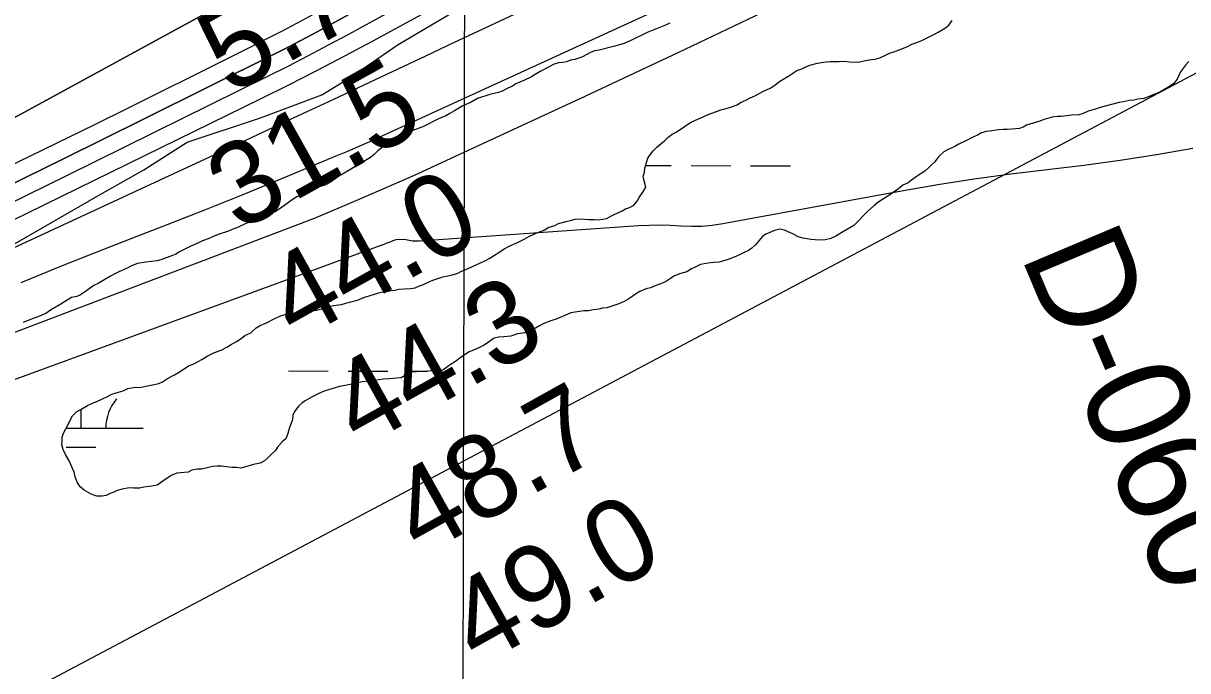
# Model space of a CAD drawing. Extents: x 3177385 to 3215275, y 903885 to 929304.
# Drawn here: x 3191696 to 3192634, y 909863 to 910384 of the extents above; entities that cross this region are included whole.
import ezdxf

# ---------------------------------------------------------------- set-up
doc = ezdxf.new("R2010")
doc.units = 0
for name, color, linetype in [('V-GRID-MAJR', 7, 'Continuous'), ('V-RIVR-EDGE', 7, 'Continuous'), ('V-RIVR-RANG', 7, 'Continuous'), ('V-RIVR-RANG-IDEN', 7, 'Continuous'), ('V-SITE-VEGE', 7, 'Continuous'), ('V-TOPO-BNDY', 7, 'Continuous'), ('V-TOPO-DPTH', 7, 'Continuous'), ('V-TOPO-MAJR', 7, 'Continuous'), ('V-TOPO-MINR', 7, 'Continuous'), ('V-TOPO-WATR', 7, 'Continuous'), ('V-WETL-SWMP', 7, 'Continuous')]:
    doc.layers.add(name, color=color, linetype=linetype)

msp = doc.modelspace()

# ---------------------------------------------------------------- linework, layer by layer
at = {"layer": 'V-GRID-MAJR'}
msp.add_spline([(3192048.7, 909312.78), (3192063.69, 915372.62), (3192078.68, 921435.55), (3192093.67, 927498.52), (3192093.68, 927501.56)], degree=3, dxfattribs=at)
at = {"layer": 'V-RIVR-EDGE'}
msp.add_lwpolyline([(3191682.14, 910203.16), (3191755.71, 910245.57), (3191792.71, 910266.35), (3191827.54, 910288.86), (3191886.7, 910308.28), (3191936.3, 910326.85), (3191958.94, 910340.7), (3191997.69, 910367.55), (3192065.17, 910407.38), (3192148.3, 910451.94), (3192242.33, 910509.96), (3192325.92, 910560.17), (3192385.98, 910590.89), (3192445.62, 910628.56), (3192497.01, 910665.38), (3192548.4, 910708.72), (3192599.37, 910750.32), (3192650.72, 910773.67)], dxfattribs=at)
at = {"layer": 'V-SITE-VEGE'}
for p, q in [((3192213.22, 910383.04), (3192206.4, 910380.34)), ((3192216.53, 910384.5), (3192213.22, 910383.04)), ((3192198.46, 910377.02), (3192184.56, 910370.33)), ((3192206.4, 910380.34), (3192198.46, 910377.02)), ((3192171.15, 910365.81), (3192159.73, 910362.78)), ((3192179.06, 910368.04), (3192171.15, 910365.81)), ((3192184.56, 910370.33), (3192179.06, 910368.04)), ((3192136.63, 910354.75), (3192133.33, 910353.51)), ((3192137.06, 910354.74), (3192136.63, 910354.75)), ((3192140.13, 910355.33), (3192137.06, 910354.74)), ((3192143.21, 910356.36), (3192140.13, 910355.33)), ((3192146.3, 910357.6), (3192143.21, 910356.36)), ((3192152.7, 910360.96), (3192146.3, 910357.6)), ((3192155.78, 910362.2), (3192152.7, 910360.96)), ((3192159.73, 910362.78), (3192155.78, 910362.2)), ((3192111.98, 910345.67), (3192108.21, 910343.13)), ((3192123.46, 910351.54), (3192111.98, 910345.67)), ((3192126.98, 910352.77), (3192123.46, 910351.54)), ((3192130.26, 910352.92), (3192126.98, 910352.77)), ((3192133.33, 910353.51), (3192130.26, 910352.92)), ((3192098.94, 910338.3), (3192092.55, 910335.6)), ((3192105.12, 910341.45), (3192098.94, 910338.3)), ((3192108.21, 910343.13), (3192105.12, 910341.45)), ((3192071.62, 910327.09), (3192061.5, 910323.82)), ((3192078.42, 910328.7), (3192071.62, 910327.09)), ((3192081.51, 910329.94), (3192078.42, 910328.7)), ((3192086.14, 910332.24), (3192081.51, 910329.94)), ((3192089.23, 910333.49), (3192086.14, 910332.24)), ((3192092.55, 910335.6), (3192089.23, 910333.49)), ((3192049.81, 910317.95), (3192042.95, 910313.95)), ((3192056.42, 910321.09), (3192049.81, 910317.95)), ((3192061.5, 910323.82), (3192056.42, 910321.09)), ((3192036.1, 910309.94), (3192029.71, 910307.24)), ((3192039.2, 910311.84), (3192036.1, 910309.94)), ((3192042.95, 910313.95), (3192039.2, 910311.84)), ((3192018.23, 910301.37), (3192009.42, 910298.07)), ((3192029.71, 910307.24), (3192018.23, 910301.37)), ((3191993.75, 910290.1), (3191990.87, 910288.42)), ((3191996.83, 910291.35), (3191993.75, 910290.1)), ((3192001.7, 910294.3), (3191996.83, 910291.35)), ((3192009.42, 910298.07), (3192001.7, 910294.3)), ((3191981.34, 910281.63), (3191978.44, 910278.85)), ((3191985.11, 910284.61), (3191981.34, 910281.63)), ((3191990.87, 910288.42), (3191985.11, 910284.61)), ((3191970.02, 910273.14), (3191960.07, 910267.24)), ((3191975.33, 910276.52), (3191970.02, 910273.14)), ((3191978.44, 910278.85), (3191975.33, 910276.52)), ((3191950.56, 910261.76), (3191943.24, 910256.46)), ((3191954.31, 910263.65), (3191950.56, 910261.76)), ((3191960.07, 910267.24), (3191954.31, 910263.65)), ((3191931.14, 910251.91), (3191927.17, 910250.03)), ((3191934.87, 910252.92), (3191931.14, 910251.91)), ((3191939.27, 910254.36), (3191934.87, 910252.92)), ((3191943.24, 910256.46), (3191939.27, 910254.36)), ((3191912.37, 910242.27), (3191906.16, 910237.81)), ((3191915.91, 910244.59), (3191912.37, 910242.27)), ((3191919.22, 910246.05), (3191915.91, 910244.59)), ((3191927.17, 910250.03), (3191919.22, 910246.05)), ((3191898.63, 910232.73), (3191884.32, 910227.58)), ((3191906.16, 910237.81), (3191898.63, 910232.73)), ((3191875.06, 910223.19), (3191868.22, 910220.06)), ((3191878.14, 910224.21), (3191875.06, 910223.19)), ((3191884.32, 910227.58), (3191878.14, 910224.21)), ((3191852.59, 910214.28), (3191849.29, 910213.04)), ((3191860.95, 910217.16), (3191852.59, 910214.28)), ((3191863.82, 910218.4), (3191860.95, 910217.16)), ((3191868.22, 910220.06), (3191863.82, 910218.4)), ((3191830.12, 910204.71), (3191821.51, 910200.31)), ((3191834.31, 910206.59), (3191830.12, 910204.71)), ((3191837.39, 910207.83), (3191834.31, 910206.59)), ((3191840.04, 910209.3), (3191837.39, 910207.83)), ((3191844.66, 910210.95), (3191840.04, 910209.3)), ((3191849.29, 910213.04), (3191844.66, 910210.95)), ((3191815.77, 910197.37), (3191806.53, 910194.08)), ((3191818.63, 910198.62), (3191815.77, 910197.37)), ((3191821.51, 910200.31), (3191818.63, 910198.62)), ((3191778.65, 910187.03), (3191772.69, 910184.32)), ((3191782.83, 910189.12), (3191778.65, 910187.03)), ((3191787.68, 910190.98), (3191782.83, 910189.12)), ((3191794.26, 910192.15), (3191787.68, 910190.98)), ((3191803.45, 910193.27), (3191794.26, 910192.15)), ((3191806.53, 910194.08), (3191803.45, 910193.27)), ((3191758.55, 910176.54), (3191755.89, 910174.85)), ((3191765.85, 910180.75), (3191758.55, 910176.54)), ((3191768.94, 910182.43), (3191765.85, 910180.75)), ((3191772.69, 910184.32), (3191768.94, 910182.43)), ((3191745.04, 910167.87), (3191741.72, 910165.76)), ((3191752.36, 910173.17), (3191745.04, 910167.87)), ((3191755.89, 910174.85), (3191752.36, 910173.17)), ((3191725.84, 910158.24), (3191717.66, 910153.39)), ((3191728.72, 910160.14), (3191725.84, 910158.24)), ((3191734.47, 910163.51), (3191728.72, 910160.14)), ((3191738.86, 910164.51), (3191734.47, 910163.51)), ((3191741.72, 910165.76), (3191738.86, 910164.51)), ((3191713.89, 910150.63), (3191707.28, 910147.93)), ((3191717.66, 910153.39), (3191713.89, 910150.63)), ((3191702.88, 910146.5), (3191695.61, 910143.59)), ((3191707.28, 910147.93), (3191702.88, 910146.5))]:
    msp.add_line(p, q, dxfattribs=at)
at = {"layer": 'V-TOPO-BNDY'}
msp.add_lwpolyline([(3212104.8, 927454.99), (3211654.69, 925302.34), (3210557.14, 922651.35), (3209209.28, 920082.76), (3207894.02, 918536.94), (3206268.96, 917198.21), (3204189.96, 915875.19), (3202488.97, 914709.68), (3200913.97, 913922.16), (3198614.47, 912914.15), (3196094.47, 911748.64), (3194267.47, 911118.63), (3192912.97, 910488.63), (3191155.59, 909558.24), (3212939.67, 909531.52)], dxfattribs=at)
at = {"layer": 'V-TOPO-DPTH'}
for points in [[(3190594.76, 909767.6), (3190671.75, 909798.31), (3190886.03, 909887.07), (3190887.1, 909887.53), (3190890.24, 909888.99), (3191053.07, 909970.07), (3191135.29, 910011.58), (3191217.19, 910053.7), (3191298.62, 910096.72), (3191379.74, 910140.34), (3191862.17, 910403.27), (3191876.76, 910411.21), (3191891.35, 910419.14), (3191905.95, 910427.05), (3191920.56, 910434.96), (3192264.2, 910620.72), (3192356.7, 910671.14), (3192448.97, 910721.98), (3192540.88, 910773.46), (3192632.56, 910825.36), (3192780.37, 910909.72)], [(3192780.37, 910909.72), (3192632.56, 910825.36), (3192540.88, 910773.46), (3192448.97, 910721.98), (3192356.7, 910671.14), (3192264.2, 910620.72), (3191920.56, 910434.96), (3191905.95, 910427.05), (3191891.35, 910419.14), (3191876.76, 910411.21), (3191862.17, 910403.27), (3191379.74, 910140.34), (3191298.62, 910096.72), (3191217.19, 910053.7), (3191135.29, 910011.58), (3191053.07, 909970.07), (3190890.24, 909888.99), (3190887.1, 909887.53), (3190886.03, 909887.07), (3190671.75, 909798.31), (3190594.76, 909767.6)], [(3190773.81, 909825.22), (3190881.11, 909873.05), (3190887.07, 909875.73), (3190893.01, 909878.44), (3190898.94, 909881.19), (3190904.85, 909883.96), (3191537.07, 910183.08), (3191601.03, 910213.58), (3191664.85, 910244.35), (3191728.49, 910275.51), (3191791.99, 910306.94), (3191898.29, 910359.95), (3191908.52, 910365.13), (3191918.71, 910370.39), (3191928.83, 910375.77), (3191938.91, 910381.24), (3192121.67, 910481.72), (3192222.94, 910537.78), (3192323.99, 910594.23), (3192424.7, 910651.27), (3192525.2, 910708.7), (3192802.32, 910868.12)], [(3192802.32, 910868.12), (3192525.2, 910708.7), (3192424.7, 910651.27), (3192323.99, 910594.23), (3192222.94, 910537.78), (3192121.67, 910481.72), (3191938.91, 910381.24), (3191928.83, 910375.77), (3191918.71, 910370.39), (3191908.52, 910365.13), (3191898.29, 910359.95), (3191791.99, 910306.94), (3191728.49, 910275.51), (3191664.85, 910244.35), (3191601.03, 910213.58), (3191537.07, 910183.08), (3190904.85, 909883.96), (3190898.94, 909881.19), (3190893.01, 909878.44), (3190887.07, 909875.73), (3190881.11, 909873.05), (3190773.81, 909825.22)], [(3189907.85, 909317.76), (3190786.54, 909802.18), (3190846.26, 909830.37), (3190874.99, 909843.88), (3190903.74, 909857.33), (3190932.53, 909870.71), (3190961.34, 909884.03), (3191160.92, 909975.94), (3191289.34, 910035.62), (3191417.47, 910095.9), (3191545.17, 910157.07), (3191672.6, 910218.83), (3191886.81, 910323.58), (3191909.55, 910334.88), (3191932.19, 910346.38), (3191954.68, 910358.18), (3191977.06, 910370.17), (3192774.87, 910804.33)]]:
    msp.add_lwpolyline(points, dxfattribs=at)
at = {"layer": 'V-TOPO-MAJR'}
msp.add_lwpolyline([(3191330.66, 909999.44), (3191930.38, 910227.54), (3191958.09, 910239.21), (3191985.69, 910251.11), (3192013.15, 910263.35), (3192040.51, 910275.81), (3192144.35, 910323.91), (3192223.38, 910360.95), (3192302.17, 910398.48), (3192380.62, 910436.73), (3192458.83, 910475.47), (3192878.95, 910685.93)], dxfattribs=at)
at = {"layer": 'V-TOPO-MINR'}
for points in [[(3190594.76, 909767.6), (3190671.75, 909798.31), (3190886.03, 909887.07), (3190887.1, 909887.53), (3190890.24, 909888.99), (3191053.07, 909970.07), (3191135.29, 910011.58), (3191217.19, 910053.7), (3191298.62, 910096.72), (3191379.74, 910140.34), (3191862.17, 910403.27), (3191876.76, 910411.21), (3191891.35, 910419.14), (3191905.95, 910427.05), (3191920.56, 910434.96), (3192264.2, 910620.72), (3192356.7, 910671.14), (3192448.97, 910721.98), (3192540.88, 910773.46), (3192632.56, 910825.36), (3192780.37, 910909.72)], [(3189797.72, 909318.02), (3190760.57, 909827.55), (3190883.54, 909880.14), (3190887.06, 909881.68), (3190890.57, 909883.25), (3190894.05, 909884.88), (3190897.52, 909886.53), (3191753.14, 910303.1), (3191779.72, 910316.11), (3191806.26, 910329.19), (3191832.74, 910342.37), (3191859.19, 910355.64), (3191903.92, 910378.18), (3191907.97, 910380.25), (3191912, 910382.34), (3191916, 910384.48), (3191919.99, 910386.65), (3191990.96, 910425.75), (3192030.35, 910447.62), (3192069.63, 910469.67), (3192108.77, 910491.99), (3192147.81, 910514.47), (3192771.73, 910876.71)], [(3189907.85, 909317.76), (3190786.54, 909802.18), (3190846.26, 909830.37), (3190874.99, 909843.88), (3190903.74, 909857.33), (3190932.53, 909870.71), (3190961.34, 909884.03), (3191160.92, 909975.94), (3191289.34, 910035.62), (3191417.47, 910095.9), (3191545.17, 910157.07), (3191672.6, 910218.83), (3191886.81, 910323.58), (3191909.55, 910334.88), (3191932.19, 910346.38), (3191954.68, 910358.18), (3191977.06, 910370.17), (3192774.87, 910804.33)], [(3189871.82, 909317.84), (3190780.45, 909815.09), (3190876.44, 909859.27), (3190887.1, 909864.19), (3190897.76, 909869.11), (3190908.41, 909874.04), (3190919.06, 909878.99), (3191339.99, 910074.62), (3191438.17, 910120.67), (3191536.12, 910167.19), (3191633.74, 910214.4), (3191731.13, 910262.07), (3191892.61, 910341.82), (3191909.04, 910350.07), (3191925.41, 910358.46), (3191941.66, 910367.06), (3191957.84, 910375.8), (3192458.26, 910650.34), (3192523.47, 910686.32), (3192588.58, 910722.5), (3192653.51, 910758.98)], [(3190790.59, 909788.07), (3190864.2, 909823.81), (3190886.93, 909834.75), (3190909.71, 909845.58), (3190932.57, 909856.25), (3190955.48, 909866.81), (3191108.63, 909936.75), (3191208.12, 909982.27), (3191307.56, 910027.91), (3191406.92, 910073.72), (3191506.23, 910119.63), (3191875.4, 910290.66), (3191910.32, 910306.88), (3191945.21, 910323.16), (3191980.07, 910339.51), (3192014.91, 910355.91), (3192042.63, 910369), (3192091.39, 910391.8), (3192140.26, 910414.38), (3192189.29, 910436.59), (3192238.43, 910458.58), (3192563.59, 910602.63), (3192609.86, 910623.15), (3192656.13, 910643.68)], [(3191693.89, 910175.76), (3191723.31, 910187.89), (3191752.87, 910199.65), (3191782.54, 910211.16), (3191812.23, 910222.62), (3191841.86, 910234.25), (3191871.38, 910246.13), (3191900.83, 910258.19), (3191947.75, 910277.64), (3191957.05, 910281.56), (3191966.33, 910285.54), (3191975.55, 910289.63), (3191984.75, 910293.79), (3192409.43, 910488.5), (3192495.07, 910528.26), (3192580.45, 910568.56), (3192665.44, 910609.67)], [(3191156.32, 909902.81), (3191984.07, 910205.65), (3191986.44, 910206.63), (3191988.81, 910207.6), (3191991.18, 910208.57), (3191993.55, 910209.53), (3191995.95, 910210.25), (3192000.82, 910210.64), (3192003.79, 910210.21), (3192006.54, 910209.71), (3192009.3, 910209.37), (3192012.09, 910209.28), (3192014.88, 910209.35), (3192191.47, 910221.5), (3192199.98, 910221.9), (3192208.48, 910222.05), (3192216.98, 910221.84), (3192225.48, 910221.39), (3192233.96, 910221.08), (3192242.42, 910221.2), (3192250.84, 910221.97), (3192259.25, 910223.18), (3192403.37, 910249.58), (3192432.6, 910254.6), (3192461.9, 910259.2), (3192491.28, 910263.17), (3192520.73, 910266.71), (3192550.17, 910270.26), (3192579.55, 910274.26), (3192608.83, 910278.93), (3192638.05, 910284.04)]]:
    msp.add_lwpolyline(points, dxfattribs=at)
at = {"layer": 'V-TOPO-WATR'}
msp.add_lwpolyline([(3190773.81, 909825.22), (3190881.11, 909873.05), (3190887.07, 909875.73), (3190893.01, 909878.44), (3190898.94, 909881.19), (3190904.85, 909883.96), (3191537.07, 910183.08), (3191601.03, 910213.58), (3191664.85, 910244.35), (3191728.49, 910275.51), (3191791.99, 910306.94), (3191898.29, 910359.95), (3191908.52, 910365.13), (3191918.71, 910370.39), (3191928.83, 910375.77), (3191938.91, 910381.24), (3192121.67, 910481.72), (3192222.94, 910537.78), (3192323.99, 910594.23), (3192424.7, 910651.27), (3192525.2, 910708.7), (3192802.32, 910868.12)], dxfattribs=at)
at = {"layer": 'V-WETL-SWMP'}
for p, q in [((3192197.18, 910269.96), (3192217.7, 910269.92)), ((3192233.7, 910269.88), (3192265.7, 910269.8)), ((3192281.7, 910269.77), (3192313.7, 910269.69)), ((3191909.31, 910104.46), (3191941.31, 910104.39)), ((3191957.31, 910104.35), (3191989.31, 910104.27)), ((3192005.31, 910104.24), (3192021.27, 910104.2)), ((3191742.14, 910058.42), (3191742.18, 910073.58)), ((3191730.26, 910058.45), (3191792.14, 910058.3)), ((3191730.11, 910043.02), (3191754.11, 910042.96))]:
    msp.add_line(p, q, dxfattribs=at)
for points in [[(3192254.27, 910313.43), (3192257.73, 910314.89), (3192260.8, 910315.58), (3192264.63, 910316.64), (3192270.77, 910318.8), (3192273.48, 910320.65), (3192277.71, 910322.46), (3192280.8, 910324.3), (3192285.03, 910326.12), (3192291.97, 910329.78), (3192297.36, 910332.34), (3192300.45, 910334.18), (3192305.09, 910337.51), (3192308.57, 910339.72), (3192312.44, 910342.31), (3192319, 910346.36), (3192322.84, 910347.8), (3192325.54, 910349.27), (3192329.39, 910350.71), (3192335.52, 910352.49), (3192338.58, 910352.8), (3192342.78, 910353.47), (3192345.84, 910353.79), (3192349.27, 910353.72), (3192353.08, 910353.64), (3192357.66, 910353.92), (3192361.08, 910353.47), (3192368.7, 910353.3), (3192371.76, 910354), (3192375.97, 910354.67), (3192379.03, 910355.37), (3192382.09, 910355.69), (3192385.92, 910356.75), (3192389.77, 910358.57), (3192393.62, 910360.39), (3192397.07, 910361.46), (3192403.61, 910363.99), (3192408.22, 910365.8), (3192411.69, 910367.63), (3192415.53, 910369.08), (3192420.14, 910370.88), (3192429.77, 910375.63), (3192432.86, 910377.47), (3192435.95, 910379.31), (3192438.65, 910380.78), (3192441.36, 910383.01), (3192444.11, 910386.76)], [(3192634.73, 910353.73), (3192632, 910350.74), (3192628.08, 910345.49), (3192625.28, 910339.45), (3192622.53, 910335.7), (3192617.9, 910332.75), (3192611.34, 910329.08), (3192606.73, 910327.27), (3192602.88, 910325.45), (3192598.66, 910324.01), (3192593.69, 910323.36), (3192590.62, 910322.66), (3192586.81, 910322.36), (3192582.21, 910321.31), (3192578.76, 910320.63), (3192571.49, 910318.87), (3192567.27, 910317.82), (3192562.67, 910316.39), (3192559.6, 910315.32), (3192554.61, 910313.9), (3192549.61, 910311.72), (3192546.16, 910310.65), (3192540.43, 910310.39), (3192532.03, 910309.42), (3192528.6, 910309.5), (3192524.77, 910308.82), (3192520.94, 910307.76), (3192517.88, 910307.06), (3192514.8, 910305.6), (3192504.06, 910302.4), (3192501.36, 910300.93), (3192498.29, 910299.85), (3192492.17, 910299.22), (3192488.36, 910298.92), (3192485.31, 910298.99), (3192481.49, 910298.69), (3192474.23, 910297.7), (3192471.17, 910297.38), (3192467.33, 910295.94), (3192464.63, 910294.47), (3192459.63, 910292.29), (3192455.77, 910290.09), (3192449.61, 910287.17), (3192446.14, 910285.34), (3192440.75, 910282.78), (3192437.28, 910280.95), (3192434.56, 910278.34), (3192432.22, 910275.72), (3192429.87, 910272.73), (3192427.53, 910270.49), (3192424.81, 910267.88), (3192422.09, 910265.27), (3192419, 910263.43), (3192415.13, 910260.84)], [(3191849.57, 910119.29), (3191854.94, 910121.09), (3191859.57, 910123.65), (3191862.66, 910125.49), (3191867.29, 910128.06), (3191871.16, 910130.65), (3191874.25, 910132.87), (3191878.87, 910135.06), (3191879.26, 910135.43), (3191883.15, 910139.16), (3191886.62, 910140.99), (3191891.62, 910143.17), (3191897.79, 910146.47), (3191902.41, 910148.66), (3191908.17, 910150.44), (3191911.6, 910150.75), (3191915.81, 910151.42), (3191920.77, 910151.7), (3191926.51, 910152.72), (3191931.86, 910153.37), (3191937.22, 910154.78), (3191940.3, 910155.86), (3191945.66, 910157.27), (3191952.15, 910157.89), (3191955.61, 910158.96), (3191959.44, 910160.02), (3191964.81, 910161.43), (3191970.58, 910163.98), (3191974.41, 910165.04), (3191980.17, 910166.82), (3191984, 910167.88), (3191988.59, 910168.55), (3191992.03, 910169.24), (3191995.09, 910169.55), (3191998.15, 910170.25), (3192002.73, 910170.53), (3192007.69, 910170.81), (3192011.52, 910171.49), (3192014.98, 910172.94), (3192018.05, 910174.02), (3192020.75, 910175.49), (3192025.75, 910177.67), (3192033.81, 910180.16), (3192041.47, 910181.9), (3192045.69, 910183.34), (3192048.77, 910184.8), (3192052.23, 910186.25), (3192058, 910188.79), (3192063.39, 910191.35), (3192068.01, 910193.54), (3192071.48, 910195.37), (3192074.57, 910197.21), (3192079.6, 910200.53), (3192083.07, 910202.74), (3192087.7, 910205.31), (3192093.85, 910207.85), (3192099.63, 910210.77), (3192103.49, 910212.98), (3192108.88, 910215.53), (3192115.8, 910218.05), (3192118.5, 910219.9), (3192123.88, 910221.69), (3192126.96, 910223.15), (3192133.09, 910224.93), (3192137.31, 910225.98), (3192140.37, 910226.68), (3192144.19, 910226.98), (3192151.42, 910226.44), (3192155.61, 910226.35), (3192159.04, 910226.28), (3192162.48, 910226.59), (3192165.54, 910227.28), (3192170.55, 910229.85), (3192178.25, 910233.49), (3192180.95, 910234.96), (3192184.02, 910236.04), (3192187.49, 910237.87), (3192190.23, 910241.24), (3192191.82, 910244.26), (3192195.35, 910249.14), (3192197.33, 910252.52), (3192195.91, 910257.51), (3192195.23, 910261.33), (3192196.06, 910264.37), (3192196.51, 910267.79), (3192198.97, 910275.74), (3192200.55, 910278.37), (3192203.29, 910281.74), (3192206.41, 910285.11), (3192212.23, 910289.94), (3192214.95, 910292.55), (3192218.44, 910295.14), (3192221.14, 910296.61), (3192228.09, 910301.03), (3192231.19, 910303.25), (3192233.89, 910304.72), (3192239.67, 910307.65), (3192243.51, 910309.09), (3192246.21, 910310.56), (3192250.43, 910311.99), (3192254.27, 910313.43)], [(3192415.13, 910260.84), (3192411.26, 910258.26), (3192408.55, 910256.03), (3192404.32, 910254.21), (3192400.82, 910251.24), (3192396.57, 910248.28), (3192393.86, 910246.43), (3192388.84, 910243.11), (3192384.2, 910240.16), (3192380.71, 910237.18), (3192376.05, 910233.09), (3192371.77, 910228.99), (3192369.8, 910226.36), (3192364.75, 910221.52), (3192356.64, 910216.73), (3192350.46, 910213.05), (3192346.23, 910211.24), (3192341.64, 910210.19), (3192337.06, 910209.91), (3192330.59, 910210.43), (3192324.13, 910211.33), (3192319.96, 910212.56), (3192315.82, 910214.94), (3192312.05, 910216.54), (3192309.02, 910217.75), (3192305.23, 910218.59), (3192301.01, 910217.54), (3192297.17, 910216.1), (3192294.09, 910214.64), (3192291, 910212.42), (3192285.52, 910206.05), (3192282.8, 910203.44), (3192280.09, 910201.6), (3192276.62, 910199.76), (3192272.77, 910197.94), (3192268.54, 910196.12), (3192263.55, 910194.33), (3192256.26, 910192.19), (3192252.06, 910191.9), (3192247.1, 910191.25), (3192241.36, 910190.22), (3192237.51, 910188.4), (3192234.04, 910186.57), (3192230.18, 910184.36), (3192224.42, 910182.58), (3192219.81, 910180.77), (3192217.11, 910178.93), (3192213.24, 910176.34), (3192207.86, 910174.17), (3192204.78, 910173.09), (3192200.93, 910171.27), (3192197.49, 910170.58), (3192192.49, 910168.4), (3192189.01, 910166.18), (3192183.6, 910162.49), (3192179.74, 910160.28), (3192175.51, 910158.47), (3192169.75, 910156.69), (3192165.91, 910155.24), (3192162.47, 910154.94), (3192159.41, 910154.24), (3192154.82, 910153.57), (3192151, 910152.89), (3192147.19, 910152.97), (3192136.86, 910151.29), (3192133.78, 910149.83), (3192124.94, 910146.21), (3192120.71, 910144.77), (3192114.95, 910142.61), (3192111.48, 910140.78), (3192108.39, 910138.94), (3192104.93, 910137.49), (3192101.08, 910135.66), (3192098.02, 910134.96), (3192093.81, 910134.29), (3192088.44, 910132.5), (3192082.71, 910131.86), (3192078.51, 910131.57), (3192075.06, 910130.88), (3192071.2, 910128.29), (3192066.94, 910125.34), (3192064.24, 910123.87), (3192060.39, 910122.05), (3192054.24, 910119.51), (3192047.28, 910114.7), (3192043.79, 910112.11), (3192040.32, 910109.9), (3192033.73, 910105.08), (3192030.29, 910104.39), (3192026.1, 910104.48), (3192016.56, 910103.92), (3192012.36, 910103.63), (3192009.31, 910103.7), (3192002.76, 910100.41), (3192000.06, 910098.94), (3191996.63, 910098.63), (3191993.57, 910098.31), (3191990.52, 910098), (3191985.56, 910097.72), (3191978.67, 910096.73), (3191973.32, 910096.08)], [(3191973.32, 910096.08), (3191968.74, 910095.79), (3191963.38, 910094.38), (3191954.96, 910092.66), (3191950.37, 910091.99), (3191946.92, 910090.92), (3191941.54, 910089.13), (3191938.09, 910088.06), (3191933.86, 910086.25), (3191928.47, 910083.69), (3191922.68, 910080.39), (3191919.97, 910078.54), (3191917.64, 910076.3), (3191914.11, 910071.8), (3191912.91, 910068.78), (3191912.44, 910064.98), (3191910.03, 910058.93), (3191908.78, 910054), (3191907.17, 910049.85), (3191904.45, 910047.62), (3191900.54, 910043.13), (3191898.96, 910040.49), (3191895.46, 910037.14), (3191892.35, 910034.15), (3191890.02, 910031.92), (3191886.55, 910030.08), (3191881.19, 910029.06), (3191873.9, 910026.92), (3191870.84, 910026.23), (3191867.42, 910026.68), (3191863.61, 910026.76), (3191859.04, 910027.24), (3191855.24, 910027.7), (3191851.81, 910027.78), (3191848, 910027.48), (3191842.63, 910026.07), (3191839.19, 910025.38), (3191835.76, 910025.45), (3191831.54, 910024.4), (3191828.46, 910022.94), (3191822.35, 910022.31), (3191819.29, 910021.99), (3191814.68, 910020.18), (3191808.88, 910016.11), (3191806.17, 910014.26), (3191803.46, 910012.42), (3191799.26, 910011.74), (3191792.76, 910010.74), (3191789.31, 910010.05), (3191784.74, 910010.15), (3191780.93, 910010.23), (3191775.19, 910009.21), (3191771.36, 910008.15), (3191768.66, 910006.68), (3191765.59, 910005.6), (3191762.51, 910004.14), (3191759.06, 910003.45), (3191754.87, 910003.54), (3191750.33, 910005.16), (3191744.68, 910008.33), (3191741.31, 910011.07), (3191739.11, 910014.93), (3191737.29, 910019.16), (3191736.61, 910022.99), (3191734.8, 910027.22), (3191732.24, 910032.61), (3191729.67, 910037.24), (3191727.85, 910041.09), (3191726.79, 910044.92), (3191726.85, 910047.97), (3191726.92, 910051.02), (3191728.13, 910054.42), (3191732.11, 910061.96), (3191733.7, 910065.35), (3191735.29, 910068.37), (3191738.79, 910071.73), (3191741.49, 910073.19), (3191747.28, 910076.5), (3191750.75, 910078.33), (3191755.36, 910080.14), (3191763.44, 910083.78), (3191766.91, 910085.61), (3191770.36, 910086.68), (3191776.12, 910088.46), (3191779.97, 910090.29), (3191785.71, 910091.31), (3191789.52, 910091.23), (3191794.49, 910092.26), (3191799.85, 910093.29), (3191804.83, 910094.33), (3191807.91, 910095.79), (3191811.77, 910098.37), (3191817.55, 910101.3), (3191820.64, 910103.14), (3191824.51, 910105.73), (3191828.76, 910108.68), (3191832.99, 910110.12), (3191836.46, 910111.95), (3191839.54, 910113.79), (3191843.79, 910116.37), (3191849.57, 910119.29)]]:
    msp.add_lwpolyline(points, dxfattribs=at)
msp.add_arc((3191797.39, 910058.77), 35.25, 139.09484, 180.63849, dxfattribs=at)

# ---------------------------------------------------------------- texts
at = {"layer": 'V-RIVR-RANG'}
for s, rotation, p in [('5.7', 29.53194, (3191862.36, 910326.07)), ('31.5', 29.14833, (3191869.17, 910215.91)), ('44.0', 29.14833, (3191915.56, 910127.28)), ('44.3', 29.14833, (3191967.02, 910041.48)), ('48.7', 29.14833, (3192015.95, 909954.27)), ('49.0', 29.14833, (3192062.34, 909865.64))]:
    msp.add_text(s, height=67, rotation=rotation, dxfattribs=at).set_placement(p)
at = {"layer": 'V-RIVR-RANG-IDEN'}
msp.add_text('D-060', height=83, rotation=292.8663, dxfattribs=at).set_placement((3192498.68, 910197.92))

doc.saveas('drawing.dxf')
